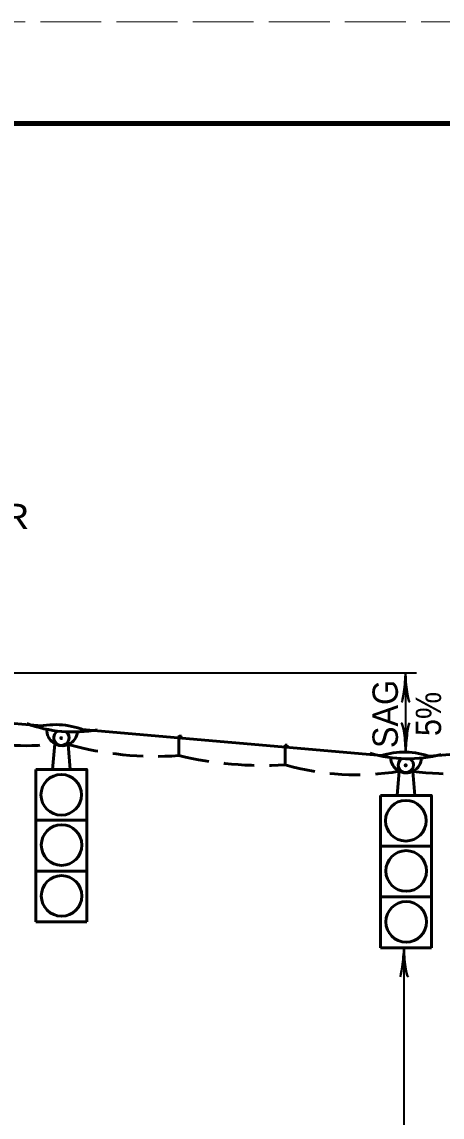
# Model space of a CAD drawing. Extents: x 12366 to 13046, y 9129 to 9570.
# Drawn here: x 12521.7 to 12563.1, y 9461.7 to 9569.5 of the extents above; entities that cross this region are included whole.
import ezdxf
from ezdxf.enums import TextEntityAlignment as Align

# ---------------------------------------------------------------- set-up
doc = ezdxf.new("R2010")
doc.units = 0
doc.linetypes.add('LONG_DASHED', pattern=[7.5, 6, -1.5])
doc.linetypes.add('MEDIUM_DASHED', pattern=[4.5, 3, -1.5])
doc.layers.add('1', color=7, linetype='Continuous', lineweight=53)
doc.layers.add('61', color=7, linetype='Continuous', lineweight=35)

msp = doc.modelspace()

# ---------------------------------------------------------------- linework, layer by layer
at = {"layer": '1', "lineweight": 35}
for p, q in [((12476.534, 9505.477), (12560.545, 9505.477)), ((12559.466, 9505.461), (12559.466, 9497.658)), ((12559.307, 9478.407), (12559.307, 9394.186))]:
    msp.add_line(p, q, dxfattribs=at)
at = {"layer": '1'}
for p, q in [((12487.527, 9503.403), (12523.636, 9500.244)), ((12632.351, 9503.418), (12561.823, 9497.248)), ((12527.62, 9499.895), (12557.105, 9497.316)), ((12537.147, 9499.264), (12537.13, 9499.065)), ((12537.143, 9499.214), (12537.13, 9499.065)), ((12537.13, 9499.065), (12537.279, 9499.051)), ((12537.13, 9499.065), (12537.13, 9497.315)), ((12537.13, 9499.065), (12537.329, 9499.047)), ((12537.161, 9499.263), (12537.143, 9499.063)), ((12537.143, 9499.214), (12537.292, 9499.201)), ((12537.156, 9499.213), (12537.143, 9499.063)), ((12537.147, 9499.264), (12537.347, 9499.246)), ((12537.176, 9499.261), (12537.158, 9499.062)), ((12537.172, 9499.211), (12537.158, 9499.062)), ((12537.191, 9499.26), (12537.174, 9499.061)), ((12537.187, 9499.21), (12537.174, 9499.061)), ((12537.206, 9499.259), (12537.189, 9499.059)), ((12537.202, 9499.209), (12537.189, 9499.059)), ((12537.214, 9499.258), (12537.197, 9499.059)), ((12537.225, 9499.257), (12537.207, 9499.058)), ((12537.22, 9499.207), (12537.207, 9499.058)), ((12537.236, 9499.256), (12537.218, 9499.057)), ((12537.232, 9499.206), (12537.218, 9499.057)), ((12537.247, 9499.255), (12537.229, 9499.056)), ((12537.255, 9499.254), (12537.238, 9499.055)), ((12537.251, 9499.204), (12537.238, 9499.055)), ((12537.27, 9499.253), (12537.253, 9499.054)), ((12537.266, 9499.203), (12537.253, 9499.054)), ((12537.285, 9499.252), (12537.267, 9499.052)), ((12537.281, 9499.202), (12537.267, 9499.052)), ((12537.297, 9499.251), (12537.279, 9499.051)), ((12537.292, 9499.201), (12537.279, 9499.051)), ((12537.308, 9499.25), (12537.29, 9499.05)), ((12537.317, 9499.249), (12537.3, 9499.05)), ((12537.327, 9499.248), (12537.31, 9499.049)), ((12537.337, 9499.247), (12537.32, 9499.048)), ((12537.347, 9499.246), (12537.329, 9499.047)), ((12524.898, 9498.481), (12524.677, 9495.959)), ((12526.214, 9498.418), (12526.429, 9495.959)), ((12547.607, 9498.349), (12547.59, 9498.149)), ((12547.603, 9498.299), (12547.59, 9498.149)), ((12547.59, 9498.149), (12547.739, 9498.136)), ((12547.59, 9498.149), (12547.59, 9496.399)), ((12547.59, 9498.149), (12547.789, 9498.132)), ((12547.621, 9498.347), (12547.603, 9498.148)), ((12547.603, 9498.299), (12547.752, 9498.286)), ((12547.617, 9498.298), (12547.603, 9498.148)), ((12547.607, 9498.349), (12547.807, 9498.331)), ((12547.636, 9498.346), (12547.619, 9498.147)), ((12547.632, 9498.296), (12547.619, 9498.147)), ((12547.651, 9498.345), (12547.634, 9498.146)), ((12547.647, 9498.295), (12547.634, 9498.146)), ((12547.666, 9498.343), (12547.649, 9498.144)), ((12547.662, 9498.294), (12547.649, 9498.144)), ((12547.674, 9498.343), (12547.657, 9498.144)), ((12547.685, 9498.342), (12547.667, 9498.143)), ((12547.68, 9498.292), (12547.667, 9498.143)), ((12547.696, 9498.341), (12547.679, 9498.142)), ((12547.692, 9498.291), (12547.679, 9498.142)), ((12547.707, 9498.34), (12547.689, 9498.141)), ((12547.715, 9498.339), (12547.698, 9498.14)), ((12547.711, 9498.289), (12547.698, 9498.14)), ((12547.73, 9498.338), (12547.713, 9498.139)), ((12547.726, 9498.288), (12547.713, 9498.139)), ((12547.745, 9498.337), (12547.728, 9498.137)), ((12547.741, 9498.287), (12547.728, 9498.137)), ((12547.757, 9498.335), (12547.739, 9498.136)), ((12547.752, 9498.286), (12547.739, 9498.136)), ((12547.768, 9498.334), (12547.75, 9498.135)), ((12547.777, 9498.334), (12547.76, 9498.134)), ((12547.787, 9498.333), (12547.77, 9498.134)), ((12547.797, 9498.332), (12547.78, 9498.133)), ((12547.807, 9498.331), (12547.789, 9498.132)), ((12523.056, 9495.959), (12523.056, 9480.959)), ((12558.838, 9495.776), (12558.631, 9493.407)), ((12560.176, 9495.767), (12560.382, 9493.407)), ((12557.009, 9493.407), (12557.009, 9478.407)), ((12523.056, 9490.959), (12528.056, 9490.959)), ((12557.009, 9488.407), (12562.009, 9488.407)), ((12523.056, 9485.959), (12528.056, 9485.959)), ((12557.009, 9483.407), (12562.009, 9483.407)), ((12523.056, 9480.959), (12528.056, 9480.959)), ((12557.009, 9478.407), (12562.009, 9478.407))]:
    msp.add_line(p, q, dxfattribs=at)
for points in [[(12523.056, 9495.959), (12528.056, 9495.959), (12528.056, 9480.959)], [(12557.009, 9493.407), (12562.009, 9493.407), (12562.009, 9478.407)]]:
    msp.add_lwpolyline(points, dxfattribs=at)
for centre, radius in [((12525.544, 9499.041), 0.05), ((12559.476, 9496.358), 0.05), ((12525.544, 9493.462), 2), ((12559.497, 9490.91), 2), ((12525.576, 9488.515), 2), ((12559.529, 9485.963), 2), ((12525.576, 9483.505), 2), ((12559.529, 9480.952), 2)]:
    msp.add_circle(centre, radius, dxfattribs=at)
for centre, radius, start, end in [((12526.706, 9512.501), 12.861, 249.20802, 280.79205), ((12524.994, 9492.825), 7.542, 65.93579, 103.97521), ((12525.636, 9499.793), 1.5, 174.85571, 355.14305), ((12525.56, 9499.072), 0.75, 118.90311, 51.34123), ((12559.696, 9509.866), 12.861, 253.20802, 284.79205), ((12559.361, 9490.119), 7.542, 69.93579, 107.97521), ((12559.515, 9497.114), 1.5, 178.85571, 359.14305), ((12559.49, 9496.39), 0.75, 122.90311, 55.34123)]:
    msp.add_arc(centre, radius, start, end, dxfattribs=at)
at = {"layer": '1', "linetype": 'MEDIUM_DASHED'}
for centre, radius, start, end in [((12522.053, 9519.668), 21.377, 253.60216, 277.64986), ((12534.897, 9529.757), 32.52, 254.5131, 273.93693), ((12545.533, 9533.127), 36.785, 256.79458, 273.20512), ((12554.618, 9521.409), 25.979, 254.30411, 279.34864), ((12563.981, 9524.338), 28.823, 262.41333, 283)]:
    msp.add_arc(centre, radius, start, end, dxfattribs=at)
at = {"layer": '1', "lineweight": 40}
for centre, major_axis, ratio, start_param, end_param in [((12559.255, 9504.341), (-0.176, -1.756), 0.07063, 6.2823074, 8.5597026), ((12559.742, 9504.37), (-0.156, 1.786), 0.122415, 0.8963533, 3.1415927), ((12559.19, 9498.749), (0.156, -1.786), 0.122415, 0.8963533, 3.1415927), ((12559.678, 9498.779), (0.176, 1.756), 0.07063, 6.2823074, 8.5597026), ((12559.095, 9477.287), (-0.176, -1.756), 0.07063, 6.2823074, 8.5597026), ((12559.583, 9477.316), (-0.156, 1.786), 0.122415, 0.8963533, 3.1415927)]:
    msp.add_ellipse(centre, major_axis=major_axis, ratio=ratio, start_param=start_param, end_param=end_param, dxfattribs=at)
at = {"layer": '61', "linetype": 'LONG_DASHED', "lineweight": 13}
msp.add_line((12365.992, 9569.533), (13046.012, 9569.533), dxfattribs=at)
at = {"layer": '61', "lineweight": 158}
msp.add_lwpolyline([(13035.032, 9559.533), (12395.992, 9559.533), (12395.992, 9139.513)], dxfattribs=at)

# ---------------------------------------------------------------- texts
at = {"layer": '1', "width": 1.15}
msp.add_text("CLAMPS 4' ON CENTER", height=2.5, dxfattribs=at).set_placement((12478.949, 9519.608))
at = {"layer": '1'}
for s, width, p in [('SAG', 0.95, (12558.708, 9501.417)), ('5%', 0.9, (12562.968, 9501.417))]:
    msp.add_text(s, height=2.5, rotation=90, dxfattribs=dict(at, width=width)).set_placement(p, align=Align.CENTER)

doc.saveas('drawing.dxf')
